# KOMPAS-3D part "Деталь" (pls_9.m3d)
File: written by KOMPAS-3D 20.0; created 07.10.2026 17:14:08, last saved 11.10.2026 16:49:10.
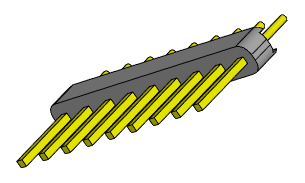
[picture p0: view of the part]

Document properties: Полное имя файла: D:\myProjects\Progect_esp32\box_compas\разъемы\pls_9.m3d

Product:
- Part/product: Деталь
    Масса: 0.00115709

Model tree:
1. Эскиз:1
2. Элемент выдавливания:1
     Расстояние 1 = 2.5
3. Эскиз:2  (with: Элемент выдавливания:1)
4. Элемент выдавливания:2
     Расстояние 1 = 6
5. Массив по сетке:1  (with: Элемент выдавливания:2, Эскиз:2)  (9 pattern instances)
     Шаг 1 = 2.54; Угол раствора = 90
6. Эскиз:3  (with: Элемент выдавливания:1)
7. Элемент выдавливания:3
     Расстояние 1 = 3
8. Массив по сетке:2  (with: Элемент выдавливания:3, Эскиз:3)  (9 pattern instances)
     Шаг 1 = 2.54; Угол раствора = 90; Геометрический массив = 128
9. Эскиз:4  (with: Элемент выдавливания:1)
10. Элемент выдавливания:4
     Расстояние 2 = 22.86
11. Скругление:1  (with: Элемент выдавливания:1)
     Радиус = 1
